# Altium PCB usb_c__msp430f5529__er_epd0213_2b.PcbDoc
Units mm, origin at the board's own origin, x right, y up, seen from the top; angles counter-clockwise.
Board outline 82 x 52 mm, 2 copper layers (Top, Bottom), stack 0 mm thick; 44 components, 39 nets, 231 pads, 105 vias.
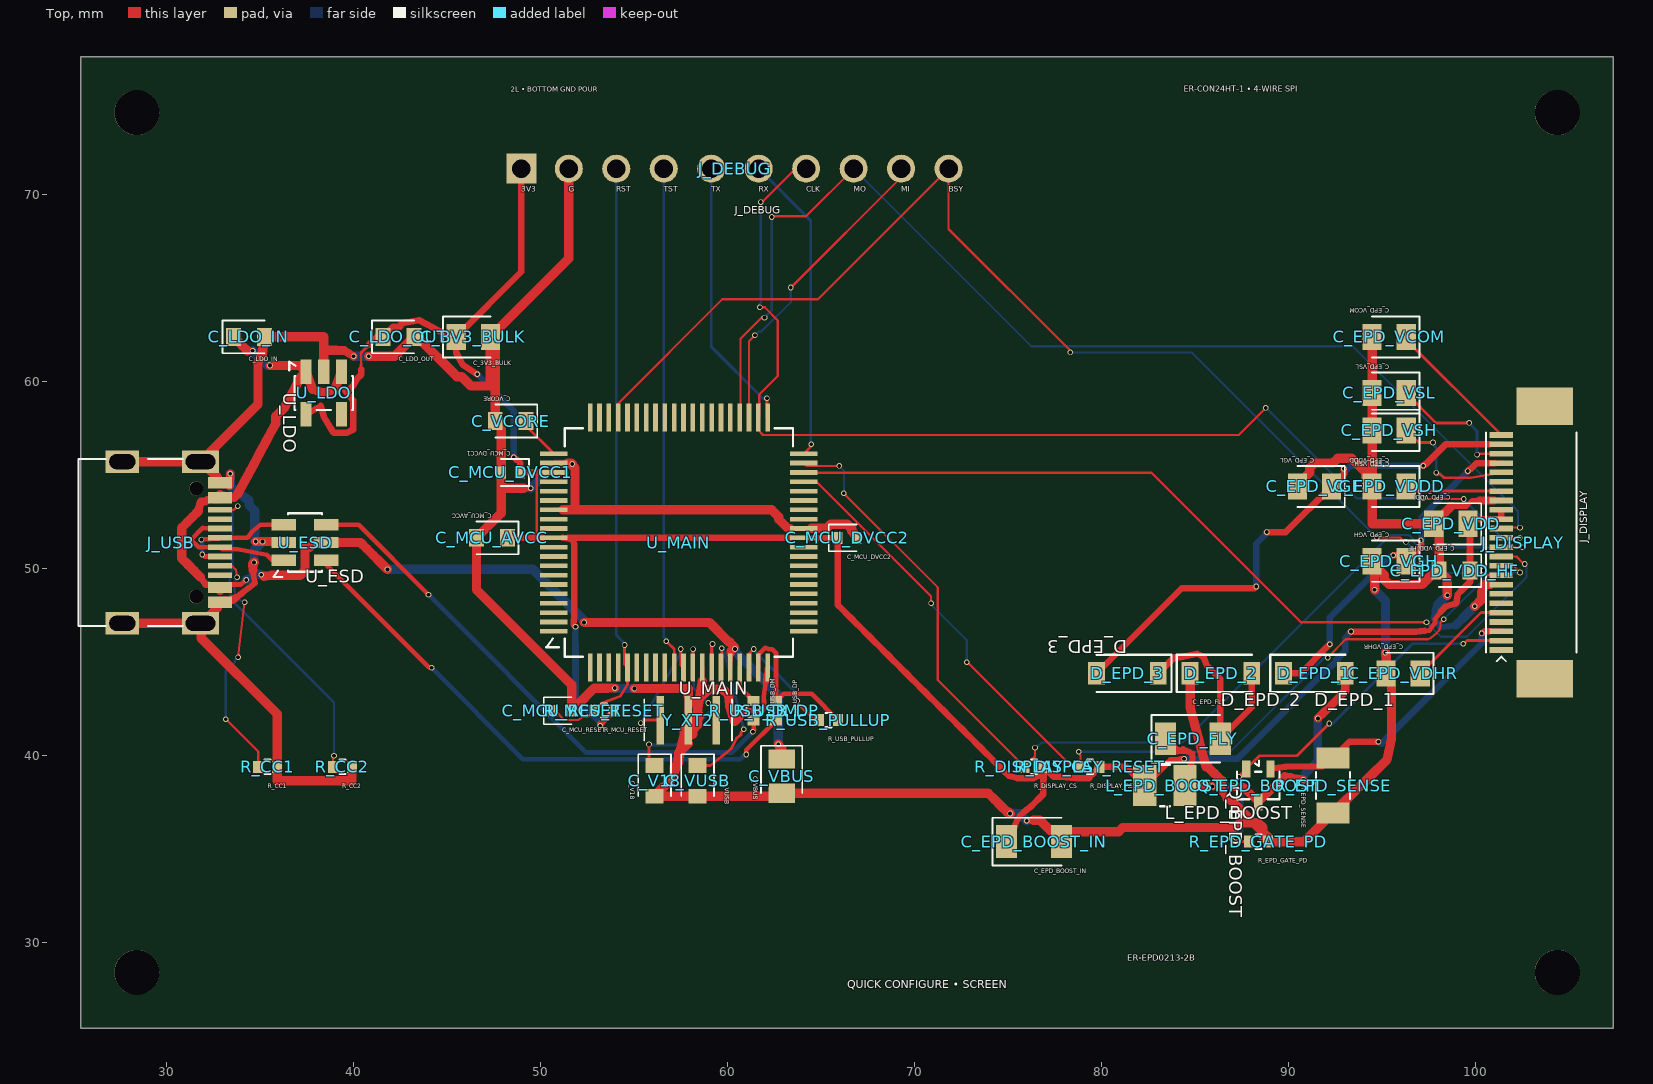
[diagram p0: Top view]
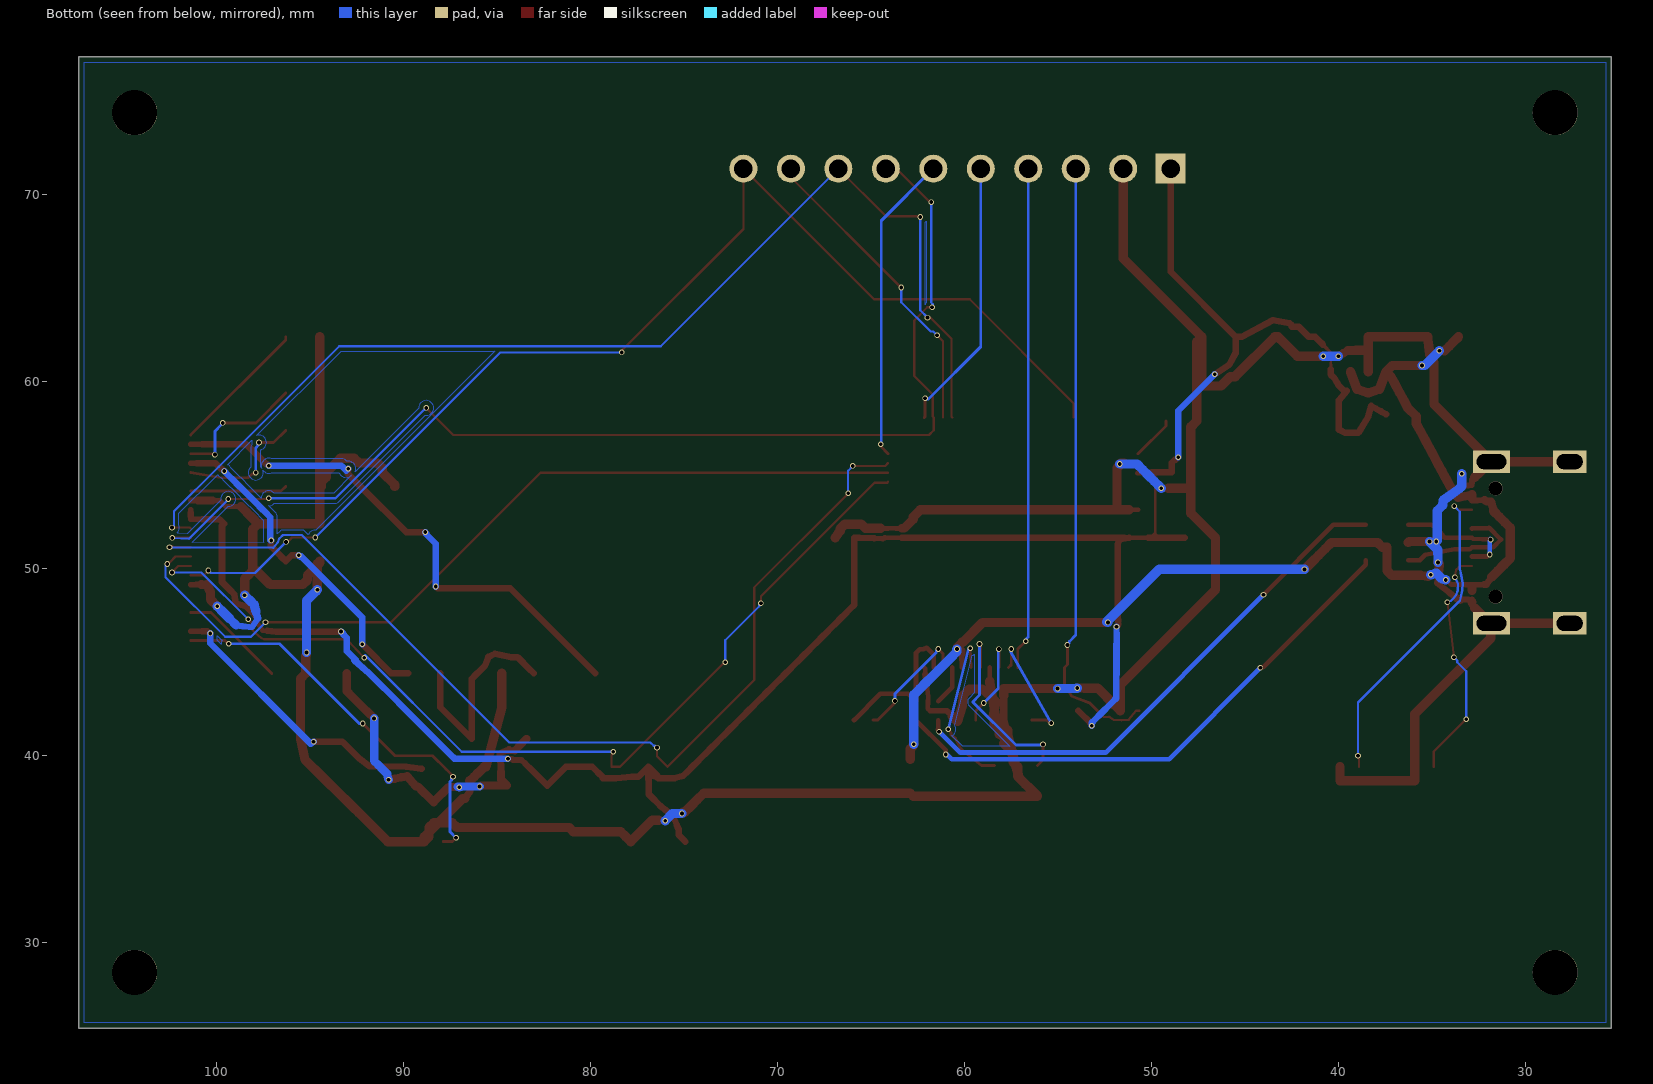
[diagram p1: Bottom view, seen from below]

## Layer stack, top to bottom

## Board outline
25.4,77.4 107.4,77.4 107.4,25.4 25.4,25.4

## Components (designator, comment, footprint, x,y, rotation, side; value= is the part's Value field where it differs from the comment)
C_3V3_BULK "" TSCIRCUIT-2.8500x1.4000mm 46.4,62.4 r0 top
C_EPD_BOOST_IN "" TSCIRCUIT-4.0500x1.7500mm 76.4,35.4 r0 top
C_EPD_FLY "" TSCIRCUIT-4.0500x1.7500mm 84.9,40.9 r0 top
C_EPD_VCOM "" TSCIRCUIT-2.8500x1.4000mm 95.4,62.4 r180 top
C_EPD_VDD "" TSCIRCUIT-2.8500x1.4000mm 98.7,52.4 r180 top
C_EPD_VDD_HF "" TSCIRCUIT-2.4500x0.9500mm 98.9,49.9 r180 top
C_EPD_VDDD "" TSCIRCUIT-2.8500x1.4000mm 95.4,54.4 r180 top
C_EPD_VDHR "" TSCIRCUIT-2.8500x1.4000mm 96.15,44.4 r180 top
C_EPD_VGH "" TSCIRCUIT-2.8500x1.4000mm 95.4,50.4 r180 top
C_EPD_VGL "" TSCIRCUIT-2.8500x1.4000mm 91.4,54.4 r180 top
C_EPD_VSH "" TSCIRCUIT-2.8500x1.4000mm 95.4,57.4 r180 top
C_EPD_VSL "" TSCIRCUIT-2.8500x1.4000mm 95.4,59.4 r180 top
C_LDO_IN "" TSCIRCUIT-2.4500x0.9500mm 34.4,62.4 r0 top
C_LDO_OUT "" TSCIRCUIT-2.4500x0.9500mm 42.4,62.4 r0 top
C_MCU_AVCC "" TSCIRCUIT-2.4500x0.9500mm 47.4,51.65 r180 top
C_MCU_DVCC1 "" TSCIRCUIT-1.5600x0.6400mm 48.4,55.15 r180 top
C_MCU_DVCC2 "" TSCIRCUIT-1.5600x0.6400mm 66.4,51.65 r0 top
C_MCU_RESET "" TSCIRCUIT-1.5600x0.6400mm 51.15,42.4 r0 top
C_V18 "" TSCIRCUIT-0.9500x2.4500mm 56.1,38.65 r270 top
C_VBUS "" TSCIRCUIT-1.4000x2.8500mm 62.9,38.9 r270 top
C_VCORE "" TSCIRCUIT-2.4500x0.9500mm 48.4,57.9 r180 top
C_VUSB "" TSCIRCUIT-0.9500x2.4500mm 58.4,38.65 r270 top
D_EPD_1 "" TSCIRCUIT-4.2000x1.2000mm 91.4,44.4 r0 top
D_EPD_2 "" TSCIRCUIT-4.2000x1.2000mm 86.4,44.4 r0 top
D_EPD_3 "" TSCIRCUIT-4.2000x1.2000mm 81.4,44.4 r180 top
J_DEBUG "" TSCIRCUIT-24.3600x1.5000mm 60.4,71.4 r0 top
J_DISPLAY "" TSCIRCUIT-4.4500x16.5800mm 103,51.4 r90 top
J_USB "" TSCIRCUIT-6.7732x9.8502mm 30.113,51.4 r90 top
L_EPD_BOOST "" TSCIRCUIT-3.4000x2.2000mm 83.4,38.4 r0 top
Q_EPD_BOOST "" TSCIRCUIT-1.7500x2.7000mm 88.4,38.4 r270 top
R_CC1 "" TSCIRCUIT-1.5600x0.6400mm 35.4,39.4 r0 top
R_CC2 "" TSCIRCUIT-1.5600x0.6400mm 39.4,39.4 r0 top
R_DISPLAY_CS "" TSCIRCUIT-1.5600x0.6400mm 76.4,39.4 r0 top
R_DISPLAY_RESET "" TSCIRCUIT-1.5600x0.6400mm 79.4,39.4 r0 top
R_EPD_GATE_PD "" TSCIRCUIT-1.5600x0.6400mm 88.4,35.4 r0 top
R_EPD_SENSE "" TSCIRCUIT-1.7500x4.0500mm 92.4,38.4 r270 top
R_MCU_RESET "" TSCIRCUIT-1.5600x0.6400mm 53.4,42.4 r0 top
R_USB_DM "" TSCIRCUIT-0.6400x1.5600mm 61.4,42.4 r90 top
R_USB_DP "" TSCIRCUIT-0.6400x1.5600mm 62.6,42.4 r90 top
R_USB_PULLUP "" TSCIRCUIT-1.5600x0.6400mm 65.4,41.9 r0 top
U_ESD "" TSCIRCUIT-3.6000x2.5000mm 37.4,51.4 r0 top
U_LDO "" TSCIRCUIT-2.5000x3.6000mm 38.4,59.4 r270 top
U_MAIN "" TSCIRCUIT-14.8500x14.8500mm 57.4,51.4 r0 top
Y_XT2 "" TSCIRCUIT-3.4000x2.6000mm 57.9,41.9 r270 top

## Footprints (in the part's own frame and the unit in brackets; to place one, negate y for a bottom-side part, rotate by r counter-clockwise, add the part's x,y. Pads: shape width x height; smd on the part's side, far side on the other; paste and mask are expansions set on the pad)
TSCIRCUIT-0.6400x1.5600mm [mm]
  rect 0.54x0.64 smd: 1(-0.51,0) 2(0.51,0)
  silkscreen extent -0.15,-0.38 0.15,0.38
TSCIRCUIT-0.9500x2.4500mm [mm]
  rect 0.8x0.95 smd: 1(-0.825,0) 2(0.825,0)
  silkscreen extent -1.43,-0.87 0.82,0.87
TSCIRCUIT-1.4000x2.8500mm [mm]
  rect 1.025x1.4 smd: 1(-0.913,0) 2(0.913,0)
  silkscreen extent -1.62,-1.1 0.91,1.1
TSCIRCUIT-1.5600x0.6400mm [mm]
  rect 0.54x0.64 smd: 1(-0.51,0) 2(0.51,0)
  silkscreen extent -0.98,-0.72 0.51,0.72
TSCIRCUIT-1.7500x2.7000mm [mm]
  rect 0.925x0.45 smd: 1(-0.888,-0.65) 2(-0.888,0.65) 3(0.887,0)
  silkscreen extent -1.32,-1.14 0.73,1.13
TSCIRCUIT-1.7500x4.0500mm [mm]
  rect 1.125x1.75 smd: 1(-1.463,0) 2(1.462,0)
  silkscreen extent -0.73,-0.91 0.73,0.91
TSCIRCUIT-2.4500x0.9500mm [mm]
  rect 0.8x0.95 smd: 1(-0.825,0) 2(0.825,0)
  silkscreen extent -1.42,-0.87 0.82,0.87
TSCIRCUIT-2.5000x3.6000mm [mm]
  rect 1.325x0.6 smd: 1(-1.137,-0.95) 2(-1.137,0) 3(-1.137,0.95) 4(1.138,0.95) 5(1.138,-0.95)
  silkscreen extent -1.69,-1.84 0.91,1.56
TSCIRCUIT-2.8500x1.4000mm [mm]
  rect 1.025x1.4 smd: 1(-0.913,0) 2(0.913,0)
  silkscreen extent -1.63,-1.1 0.91,1.1
TSCIRCUIT-3.4000x2.2000mm [mm]
  rect 1.25x2.2 smd: 1(-1.075,0) 2(1.075,0)
  silkscreen extent -0.26,-1.11 0.26,1.11
TSCIRCUIT-3.4000x2.6000mm [mm]
  rect 2.6x0.4 smd: 1(0,1.5) 2(0,0) 3(0,-1.5)
  silkscreen extent -1.1,-2.35 1.1,2.35
TSCIRCUIT-3.6000x2.5000mm [mm]
  rect 1.325x0.6 smd: 1(-1.137,-0.95) 2(-1.137,0) 3(-1.137,0.95) 4(1.138,0.95) 5(1.138,0) 6(1.138,-0.95)
  silkscreen extent -1.69,-1.84 0.91,1.56
TSCIRCUIT-4.0500x1.7500mm [mm]
  rect 1.125x1.75 smd: 1(-1.462,0) 2(1.463,0)
  silkscreen extent -2.22,-1.28 1.46,1.27
TSCIRCUIT-4.2000x1.2000mm [mm]
  rect 0.9x1.2 smd: 1(-1.65,0) 2(1.65,0)
  silkscreen extent -2.36,-1 1.65,1
TSCIRCUIT-4.4500x16.5800mm [mm]
  rect 0.3x1.25 smd: 1(-5.75,1.6) 2(-5.25,1.6) 3(-4.75,1.6) 4(-4.25,1.6) 5(-3.75,1.6) 6(-3.25,1.6) 7(-2.75,1.6) 8(-2.25,1.6) 9(-1.75,1.6) 10(-1.25,1.6) 11(-0.75,1.6) 12(-0.25,1.6) 13(0.25,1.6) 14(0.75,1.6) 15(1.25,1.6) 16(1.75,1.6) 17(2.25,1.6) 18(2.75,1.6) 19(3.25,1.6) 20(3.75,1.6) 21(4.25,1.6) 22(4.75,1.6) 23(5.25,1.6) 24(5.75,1.6)
  rect 2x3 smd: 25(7.29,-0.725) 26(-7.29,-0.725)
  silkscreen extent -6.35,-2.43 5.9,2.42
TSCIRCUIT-6.7732x9.8502mm [mm]
  rect 0.3x1.3 smd: 1(-3.35,-2.737) 2(-3.05,-2.737) 3(-2.55,-2.737) 4(-2.25,-2.737) 5(-1.75,-2.737) 6(-1.25,-2.737) 7(-0.75,-2.737) 8(-0.25,-2.737) 9(0.25,-2.737) 10(0.75,-2.737) 11(1.25,-2.737) 12(1.75,-2.737) 13(2.55,-2.737) 14(2.25,-2.737) 15(3.35,-2.737) 16(3.05,-2.737)
  rect 1.2x2 hole 0.8 slot 1.6 at 90 deg: 17(-4.325,-1.693) 18(4.325,-1.693)
  rect 1.2x1.8 hole 0.8 slot 1.4 at 90 deg: 19(4.325,2.487) 20(-4.325,2.487)
  round 0.75 hole 0.75 unplated: NPTH-1(-2.9,-1.468) NPTH-2(2.9,-1.468)
  silkscreen extent -4.47,-0.75 4.47,4.83
TSCIRCUIT-14.8500x14.8500mm [mm]
  rect 1.475x0.25 smd: 1(-6.687,-4.75) 2(-6.687,-4.25) 3(-6.687,-3.75) 4(-6.687,-3.25) 5(-6.687,-2.75) 6(-6.687,-2.25) 7(-6.687,-1.75) 8(-6.687,-1.25) 9(-6.687,-0.75) 10(-6.687,-0.25) 11(-6.687,0.25) 12(-6.687,0.75) 13(-6.687,1.25) 14(-6.687,1.75) 15(-6.687,2.25) 16(-6.687,2.75) 17(-6.687,3.25) 18(-6.687,3.75) 19(-6.687,4.25) 20(-6.687,4.75) 41(6.687,4.75) 42(6.687,4.25) 43(6.687,3.75) 44(6.687,3.25) 45(6.687,2.75) 46(6.687,2.25) 47(6.687,1.75) 48(6.687,1.25) 49(6.687,0.75) 50(6.687,0.25) 51(6.687,-0.25) 52(6.687,-0.75) 53(6.687,-1.25) 54(6.687,-1.75) 55(6.687,-2.25) 56(6.687,-2.75) 57(6.687,-3.25) 58(6.687,-3.75) 59(6.687,-4.25) 60(6.687,-4.75)
  rect 0.25x1.475 smd: 21(-4.75,6.687) 22(-4.25,6.687) 23(-3.75,6.687) 24(-3.25,6.687) 25(-2.75,6.687) 26(-2.25,6.687) 27(-1.75,6.687) 28(-1.25,6.687) 29(-0.75,6.687) 30(-0.25,6.687) 31(0.25,6.687) 32(0.75,6.687) 33(1.25,6.687) 34(1.75,6.687) 35(2.25,6.687) 36(2.75,6.687) 37(3.25,6.687) 38(3.75,6.687) 39(4.25,6.687) 40(4.75,6.687) 61(4.75,-6.687) 62(4.25,-6.687) 63(3.75,-6.687) 64(3.25,-6.687) 65(2.75,-6.687) 66(2.25,-6.687) 67(1.75,-6.687) 68(1.25,-6.687) 69(0.75,-6.687) 70(0.25,-6.687) 71(-0.25,-6.687) 72(-0.75,-6.687) 73(-1.25,-6.687) 74(-1.75,-6.687) 75(-2.25,-6.687) 76(-2.75,-6.687) 77(-3.25,-6.687) 78(-3.75,-6.687) 79(-4.25,-6.687) 80(-4.75,-6.687)
  silkscreen extent -7.09,-6.11 6.11,6.11
TSCIRCUIT-24.3600x1.5000mm [mm]
  rect 1.6x1.6 hole 1: 1(-11.43,0)
  round 1.5 hole 1: 2(-8.89,0) 3(-6.35,0) 4(-3.81,0) 5(-1.27,0) 6(1.27,0) 7(3.81,0) 8(6.35,0) 9(8.89,0) 10(11.43,0)

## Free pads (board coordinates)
  round 2.4 hole 2.4 unplated: NPTH-3(28.4,28.4) NPTH-4(104.4,28.4) NPTH-5(28.4,74.4) NPTH-6(104.4,74.4)

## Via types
v1: diameter 0.3, hole 0.2, Top to Bottom, 105 vias

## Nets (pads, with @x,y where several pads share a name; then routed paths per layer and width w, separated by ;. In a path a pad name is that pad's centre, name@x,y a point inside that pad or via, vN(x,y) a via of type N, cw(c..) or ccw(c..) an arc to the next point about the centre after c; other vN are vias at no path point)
".J_DEBUG > .pin4 to .U_MAIN > .pin71": J_DEBUG.4 U_MAIN.71 | length 26.9
  Top w0.15: v1(56.72,46.123) 57.15,45.693 U_MAIN.71
  Bottom w0.15: J_DEBUG.4 56.59,46.35 56.676,46.264 56.676,46.167 v1(56.72,46.123)
".J_DEBUG > .pin5 to .U_MAIN > .pin40": J_DEBUG.5 U_MAIN.40 | length 14.7
  Top w0.15: v1(62.108,59.119) 62.108,58.129 U_MAIN.40
  Bottom w0.15: J_DEBUG.5 59.13,61.87 61.93,59.07 62.059,59.07 v1(62.108,59.119)
".J_DEBUG > .pin6 to .U_MAIN > .pin41": J_DEBUG.6 U_MAIN.41 | length 16.6
  Top w0.15: U_MAIN.41 64.475,56.537 v1(64.475,56.651)
  Bottom w0.15: J_DEBUG.6 64.456,68.614 64.456,56.805 64.456,56.67 v1(64.475,56.651)
".J_DISPLAY > .pin5 to .C_EPD_VDHR > .pin1": C_EPD_VDHR.1 J_DISPLAY.5 | length 5.7
  Top w0.15: C_EPD_VDHR.1 100.313,47.65 J_DISPLAY.5
".J_DISPLAY > .pin18 to .C_EPD_VDDD > .pin1": C_EPD_VDDD.1 J_DISPLAY.18 | length 5.2
  Top w0.15: C_EPD_VDDD.1 96.563,54.15 J_DISPLAY.18
".J_DISPLAY > .pin20 to .C_EPD_VSH > .pin1": C_EPD_VSH.1 J_DISPLAY.20 | length 7
  Top w0.15: C_EPD_VSH.1 96.964,56.749 v1(97.742,56.749) ; v1(97.914,55.141) 97.984,55.071 98.12,55.071 98.327,54.865 99.768,54.865 J_DISPLAY.20
  Bottom w0.15: v1(97.742,56.749) 97.796,56.695 97.796,56.591 97.914,56.472 v1(97.914,55.141)
".J_DISPLAY > .pin22 to .C_EPD_VSL > .pin1": C_EPD_VSL.1 J_DISPLAY.22 | length 7.2
  Top w0.15: C_EPD_VSL.1 97.914,57.799 v1(99.681,57.799) ; v1(100.104,56.104) 100.112,56.112 100.166,56.112 100.203,56.15 J_DISPLAY.22
  Bottom w0.15: v1(99.681,57.799) 99.75,57.73 99.75,57.706 100.104,57.352 v1(100.104,56.104)
".J_DISPLAY > .pin24 to .C_EPD_VCOM > .pin1": C_EPD_VCOM.1 J_DISPLAY.24 | length 7.4
  Top w0.15: C_EPD_VCOM.1 96.312,62.238 J_DISPLAY.24
DISPLAY_BUSY_N: J_DEBUG.10 J_DISPLAY.9 U_MAIN.24 | length 64.3
  Top w0.12: U_MAIN.24 54.15,58.837 59.725,64.412 64.842,64.412 J_DEBUG.10 71.83,68.177 78.394,61.613 78.381,61.613 v1(78.337,61.569) ; v1(94.736,51.669) 95.976,51.669 96.158,51.487 96.241,51.487 v1(96.295,51.433) ; v1(100.45,49.9) 100.7,49.65 J_DISPLAY.9
  Bottom w0.12: v1(78.337,61.569) 84.836,61.569 94.733,51.672 v1(94.736,51.669) ; v1(96.295,51.433) 97.96,49.768 100.318,49.768 v1(100.45,49.9)
DISPLAY_CS_N: J_DISPLAY.12 R_DISPLAY_CS.1 U_MAIN.42 | length 55.7
  Top w0.12: U_MAIN.42 64.239,55.499 v1(65.985,55.499) ; v1(66.227,54.039) 66.31,53.956 66.31,53.934 71.244,49 71.244,48.978 71.244,44.046 R_DISPLAY_CS.1 76.453,39.963 v1(76.453,40.427) ; J_DISPLAY.12 102.336,51.15 102.381,51.195 v1(102.532,51.151)
  Bottom w0.12: v1(65.985,55.499) 66.018,55.466 66.018,55.451 66.227,55.242 v1(66.227,54.039) ; v1(76.453,40.427) 76.553,40.528 76.631,40.528 76.807,40.704 84.355,40.704 95.455,51.804 96.463,51.804 96.633,51.634 96.674,51.593 96.724,51.422 96.979,51.116 v1(102.532,51.151)
DISPLAY_DC: J_DISPLAY.11 U_MAIN.43 | length 45.8
  Top w0.12: U_MAIN.43 64.102,55.136 82.681,55.137 90.685,47.138 v1(97.395,47.134) ; J_DISPLAY.11 102.206,50.65 102.52,50.336 102.559,50.336 v1(102.65,50.248)
  Bottom w0.12: v1(97.395,47.134) 97.513,47.016 98.173,46.356 98.815,46.356 99.552,46.356 102.742,49.546 102.742,50.153 v1(102.65,50.248)
DISPLAY_MISO: J_DEBUG.9 U_MAIN.38 | length 16.8
  Top w0.12: U_MAIN.38 61.15,62.17 v1(61.466,62.486) ; v1(63.379,65.044) 63.436,65.101 63.455,65.101 69.29,70.937 J_DEBUG.9
  Bottom w0.12: v1(61.466,62.486) 61.674,62.694 61.813,62.694 63.379,64.26 v1(63.379,65.044)
DISPLAY_MOSI: J_DEBUG.8 J_DISPLAY.14 U_MAIN.37 | length 62.1
  Top w0.12: U_MAIN.37 60.702,58.139 60.702,62.301 61.833,63.432 v1(61.98,63.432) ; v1(62.371,68.813) 62.414,68.856 62.554,68.856 64.206,68.856 J_DEBUG.8 ; J_DISPLAY.14 101.45,52.2 v1(102.4,52.2)
  Bottom w0.12: v1(61.98,63.432) 62.012,63.464 62.371,63.823 v1(62.371,68.813) ; J_DEBUG.8 76.252,61.898 93.314,61.898 93.458,61.898 99.896,55.459 102.29,53.065 102.29,52.219 102.381,52.219 v1(102.4,52.2)
DISPLAY_RESET_N: J_DISPLAY.10 R_DISPLAY_RESET.1 U_MAIN.44 | length 52
  Top w0.12: U_MAIN.44 64.137,54.601 64.816,54.601 70.892,48.526 v1(70.892,48.151) ; v1(72.8,45) 72.889,44.911 72.923,44.911 78.433,39.4 R_DISPLAY_RESET.1 78.89,40.022 78.799,40.112 v1(78.799,40.203) ; v1(92.112,45.229) 93.062,46.221 97.435,46.221 97.457,46.221 97.621,46.285 97.943,46.557 98.076,46.705 98.148,46.912 98.148,47.121 v1(98.325,47.298) ; J_DISPLAY.10 102.05,50.15 v1(102.399,49.798)
  Bottom w0.12: v1(70.892,48.151) 70.98,48.063 70.98,47.995 72.8,46.175 v1(72.8,45) ; v1(78.799,40.203) 86.891,40.203 92.068,45.38 92.068,45.273 v1(92.112,45.229) ; v1(98.325,47.298) 100.827,49.8 102.308,49.8 v1(102.399,49.798)
DISPLAY_SCLK: J_DEBUG.7 J_DISPLAY.13 U_MAIN.39 | length 61.8
  Top w0.12: v1(61.735,63.982) 61.993,63.982 62.693,63.282 62.693,60.31 61.698,59.314 61.698,58.135 U_MAIN.39 61.65,57.41 61.903,57.158 87.358,57.158 v1(88.8,58.6) ; v1(61.78,69.614) 61.849,69.683 61.921,69.683 63.639,71.4 J_DEBUG.7 ; v1(97.225,53.766) 97.262,53.729 97.392,53.729 v1(99.391,53.729) ; J_DISPLAY.13 102.329,51.65 102.379,51.6 v1(102.387,51.645)
  Bottom w0.12: v1(61.735,63.982) 61.695,64.022 61.695,64.15 61.78,64.236 v1(61.78,69.614) ; v1(88.8,58.6) 88.916,58.484 88.932,58.484 93.65,53.766 v1(97.225,53.766) ; v1(99.391,53.729) 99.483,53.637 99.483,53.609 101.492,51.6 v1(102.387,51.645)
EPD_GDR: J_DISPLAY.2 Q_EPD_BOOST.1 R_EPD_GATE_PD.1 | length 21.3
  Top w0.15: v1(87.2,35.6) 87.217,35.583 87.4,35.4 R_EPD_GATE_PD.1 ; v1(87.364,38.863) 87.364,38.901 Q_EPD_BOOST.1 88.456,39.994 90.471,39.994 v1(92.193,41.716) ; v1(99.363,45.987) 99.41,46.034 99.448,46.034 99.565,46.15 J_DISPLAY.2
  Bottom w0.15: v1(87.2,35.6) 87.525,35.925 87.525,38.464 87.525,38.605 87.449,38.681 87.449,38.778 v1(87.364,38.863) ; v1(92.193,41.716) 92.195,41.718 92.382,41.718 96.651,45.987 v1(99.363,45.987)
EPD_PUMP: C_EPD_FLY.2 D_EPD_2.2 D_EPD_3.1 | length 11.7
  Top w0.35: D_EPD_3.1 83.268,44.618 83.486,44.836 83.704,45.054 83.922,45.272 84.239,45.272 85.125,45.45 85.475,45.275 85.658,44.802 85.893,44.567 86.128,44.333 86.363,44.098 86.363,43.778 86.363,43.458 86.363,43.138 86.363,42.819 86.363,42.499 86.363,42.179 86.363,41.859 86.363,41.54 86.363,41.22 C_EPD_FLY.2 88.05,42.587 D_EPD_2.2
EPD_RESE: J_DISPLAY.3 Q_EPD_BOOST.2 R_EPD_SENSE.1 | length 15.7
  Top w0.3: 100.775,46.65 100.837,46.65 100.931,46.65 101.025,46.65 101.119,46.65 101.213,46.65 101.306,46.65 J_DISPLAY.3
  Top w0.35: Q_EPD_BOOST.2 89.858,39.413 91.824,39.426 R_EPD_SENSE.1 93.279,40.741 v1(94.825,40.741) ; v1(100.353,46.535) 100.394,46.576 100.431,46.576 100.505,46.65 100.65,46.65 100.744,46.65 100.775,46.65
  Bottom w0.35: v1(94.825,40.741) 94.969,40.648 94.994,40.648 100.353,46.008 v1(100.353,46.535)
EPD_SWITCH: C_EPD_FLY.1 D_EPD_1.2 L_EPD_BOOST.2 Q_EPD_BOOST.3 | length 17.8
  Top w0.337: 84.37,40.346 84.624,40.22 84.878,40.094 84.878,39.756 84.799,39.52
  Top w0.35: 84.069,40.269 84.443,40.269 84.37,40.346
  Top w0.375: L_EPD_BOOST.2@84.798,39.121 84.799,39.52
  Top w0.413: C_EPD_FLY.1 83.753,40.584 84.069,40.269
  Top w0.45: L_EPD_BOOST.2@84.798,39.121 84.796,38.721 84.636,38.561 L_EPD_BOOST.2 85.877,38.4 85.93,38.346 v1(85.943,38.347) ; v1(87.032,38.311) 87.593,38.319 Q_EPD_BOOST.3 88.681,37.788 88.962,38.064 89.243,38.34 89.35,38.35 89.805,38.892 90.14,38.831 90.475,38.769 v1(90.81,38.707) ; v1(91.589,41.988) 91.602,42.001 91.891,42.29 92.181,42.58 92.471,42.87 92.76,43.159 93.05,43.449 93.05,43.766 93.05,44.083 D_EPD_1.2
  Bottom w0.45: v1(85.943,38.347) 86.936,38.347 86.94,38.343 87.109,38.343 v1(87.032,38.311) ; v1(90.81,38.707) 90.894,39 90.894,39.027 91.126,39.258 91.357,39.49 91.589,39.722 91.589,40.099 91.589,40.477 91.589,40.855 91.589,41.233 91.589,41.61 v1(91.589,41.988)
EPD_VGH: C_EPD_VGH.1 D_EPD_1.1 J_DISPLAY.21 | length 18.4
  Top w0.3: J_DISPLAY.21@101.071,55.65 J_DISPLAY.21
  Top w0.325: v1(97.09,51.51) 97.124,51.211
  Top w0.35: D_EPD_1.1 90.683,44.405 92.13,45.874 92.146,45.88 v1(92.221,45.955) ; v1(95.619,50.721) 95.992,50.721 C_EPD_VGH.1 96.515,50.603 96.718,50.805 96.921,51.008 97.124,51.211 ; v1(99.605,55.221) 99.728,55.344 99.777,55.344 99.93,55.497 100.083,55.65 100.412,55.65 100.741,55.65 J_DISPLAY.21@101.071,55.65
  Bottom w0.35: v1(92.221,45.955) 92.221,47.391 95.481,50.65 95.548,50.65 v1(95.619,50.721) ; v1(97.09,51.51) 97.14,51.522 97.14,51.83 97.14,52.139 97.14,52.448 97.14,52.756 97.387,53.003 97.633,53.249 97.88,53.496 98.126,53.742 98.373,53.989 98.619,54.235 98.866,54.482 99.112,54.728 99.359,54.975 v1(99.605,55.221)
EPD_VGL: C_EPD_VGL.1 D_EPD_3.2 J_DISPLAY.23 | length 28.4
  Top w0.3: 100.775,56.65 100.837,56.65 100.931,56.65 101.025,56.65 101.119,56.65 101.213,56.65 101.306,56.65 J_DISPLAY.23
  Top w0.35: D_EPD_3.2 84.3,48.95 88.115,48.95 88.189,48.95 v1(88.283,49.044) ; v1(88.852,51.958) 89.871,51.958 C_EPD_VGL.1 92.985,55.072 v1(92.966,55.348) ; v1(97.22,55.505) 97.292,55.577 97.345,55.577 98.418,56.65 100.65,56.65 100.744,56.65 100.775,56.65
  Bottom w0.35: v1(88.283,49.044) 88.289,51.334 88.794,51.839 88.794,51.9 v1(88.852,51.958) ; v1(92.966,55.348) 93.076,55.307 93.076,55.247 93.334,55.505 v1(97.22,55.505)
GND: C_3V3_BULK.2 C_EPD_BOOST_IN.2 C_EPD_VCOM.2 C_EPD_VDD.2 C_EPD_VDD_HF.2 C_EPD_VDDD.2 C_EPD_VDHR.2 C_EPD_VGH.2 C_EPD_VGL.2 C_EPD_VSH.2 C_EPD_VSL.2 C_LDO_IN.2 C_LDO_OUT.2 C_MCU_AVCC.2 C_MCU_DVCC1.2 C_MCU_DVCC2.2 C_MCU_RESET.2 C_V18.2 C_VBUS.2 C_VCORE.2 C_VUSB.2 D_EPD_2.1 J_DEBUG.2 J_DISPLAY.8 J_DISPLAY.17 J_USB.1 J_USB.2 J_USB.15 J_USB.16 J_USB.17 J_USB.18 J_USB.19 J_USB.20 R_CC1.2 R_CC2.2 R_EPD_GATE_PD.2 R_EPD_SENSE.2 U_ESD.2 U_LDO.2 U_MAIN.14 U_MAIN.19 U_MAIN.49 U_MAIN.61 U_MAIN.68 Y_XT2.2 | length 268.7
  Top w0.25: U_MAIN.14@51.203,53.15 U_MAIN.14 U_MAIN.14@51.45,53.15 ; U_MAIN.68@58.65,43.975 U_MAIN.68 ; 61.962,42.525 61.955,42.846 61.948,43.166 61.999,43.555 62.049,43.945 ; U_MAIN.61@62.099,44.334 62.099,44.661 U_MAIN.61 ; U_MAIN.49@63.658,52.158 U_MAIN.49 ; 98.717,53.33 99.533,53.33 99.852,53.65 100.239,53.65 ; U_MAIN.19 51.144,55.65 51.45,55.65 51.369,55.65 51.275,55.65 51.181,55.65 51.088,55.65 50.994,55.65 50.9,55.65 50.806,55.65 U_MAIN.19
  Top w0.269: U_MAIN.49 U_MAIN.49@64.494,52.155
  Top w0.275: J_USB.1@32.849,48.2 J_USB.2 ; 60.95,42.4 61.306,42.4 61.572,42.4 61.837,42.4 61.962,42.525
  Top w0.277: U_MAIN.49@63.35,52.163 U_MAIN.49@63.658,52.158
  Top w0.288: J_USB.15@32.849,54.6 J_USB.16 J_USB.16@32.945,54.461
  Top w0.3: J_USB.1@32.699,47.9 J_USB.1 J_USB.2@32.849,48.2 ; 32.699,54.9 J_USB.15 J_USB.16@32.849,54.6 ; J_USB.2 32.945,48.339 33.037,48.35 33.13,48.35 33.224,48.35 33.318,48.35 33.412,48.35 33.499,48.35 ; J_USB.16@32.945,54.461 33.037,54.45 33.13,54.45 33.224,54.45 33.318,54.45 J_USB.16@33.349,54.45 ; 60.662,42.111 60.95,42.4 ; J_DISPLAY.17@101.013,53.65 J_DISPLAY.17 ; J_DISPLAY.8@101.108,49.15 J_DISPLAY.8
  Top w0.31: 34.383,48.964 34.73,49.231
  Top w0.312: 34.631,49.658 34.73,49.231 ; 49.102,54.305 v1(49.469,54.305)
  Top w0.322: J_DISPLAY.8@100.817,49.145 J_DISPLAY.8@101.108,49.15
  Top w0.325: 34.036,48.696 34.383,48.964 ; 34.612,49.932 34.631,49.658 ; 62.049,43.945 U_MAIN.61@62.099,44.334
  Top w0.35: 33.689,48.429 34.036,48.696 ; v1(76.015,36.52) 76.365,36.534
  Top w0.375: 86.462,38.65 86.462,38.369 86.462,38.088 86.721,37.707
  Top w0.4: Y_XT2.2@57.7,41.149 Y_XT2.2 57.9,43.2 ; Y_XT2.2@57.9,40.65 57.9,40.9 58.15,41.15
  Top w0.425: 33.557,48.35 33.689,48.429 ; 100.239,53.65 100.626,53.65
  Top w0.437: 39.494,61.681 39.745,61.524 v1(39.996,61.367) ; 100.626,53.65 J_DISPLAY.17@101.013,53.65
  Top w0.45: 33.505,48.35 33.557,48.35
  Top w0.475: J_USB.16@33.349,54.45 v1(33.4,55.075) ; 39.056,61.681 39.494,61.681 ; 62.743,52.65 63.009,52.384 63.228,52.166 63.35,52.163 ; 98.407,53.02 98.717,53.33 ; 100.525,49.14 J_DISPLAY.8@100.817,49.145
  Top w0.5: J_USB.20 J_USB.17 ; J_USB.19 J_USB.18 ; J_USB.1@32.699,47.9 32.474,47.675 31.874,47.075 J_USB.17 ; 32.699,54.9 32.474,55.125 31.874,55.725 J_USB.18 ; 33.499,48.35 33.505,48.35 ; 34.612,49.932 34.593,50.206 34.593,50.255 v1(34.674,50.336) ; v1(34.765,51.456) 35.246,51.456 35.726,51.456 36.207,51.456 U_ESD.2 36.213,51.45 v1(35.125,51.45) ; 39.056,61.681 38.4,61.681 U_LDO.2 38.4,62.4 C_LDO_IN.2 35.169,61.93 35.112,61.46 34.882,61.053 34.882,58.801 J_USB.18 ; R_CC2.2 39.91,38.65 35.91,38.65 R_CC1.2 35.91,42.222 31.838,46.294 31.838,47.043 J_USB.17 ; v1(40.804,61.361) 40.809,61.366 40.903,61.366 41.333,61.366 41.762,61.366 42.191,61.366 42.536,61.711 42.88,62.055 C_LDO_OUT.2 43.4,62.4 45.525,60.275 45.775,60.275 46.275,59.775 47.313,59.775 C_3V3_BULK.2 ; 49.102,54.305 48.735,54.305 47.89,54.305 C_MCU_DVCC1.2 ; U_MAIN.14@51.203,53.15 51.693,53.15 52.183,53.15 52.673,53.15 53.164,53.15 62.361,53.15 62.743,52.767 62.743,52.65 ; 51.45,53.15 51.84,53.15 51.84,55.385 51.575,55.65 51.45,55.65 51.463,55.65 51.642,55.65 51.692,55.6 v1(51.7,55.6) ; J_DEBUG.2 51.51,66.597 C_3V3_BULK.2 ; v1(53.968,43.613) 53.602,43.612 53.236,43.611 52.87,43.61 52.567,43.308 52.265,43.005 51.962,42.703 C_MCU_RESET.2 51.66,43.788 46.575,48.873 46.575,49.336 46.575,49.799 46.575,50.262 46.575,50.724 46.575,51.187 C_MCU_AVCC.2 47.89,52.965 C_MCU_DVCC1.2 ; v1(55.019,43.586) 57.9,43.586 57.9,43.2 ; 57.7,41.149 57.074,38.799 56.749,38.474 56.425,38.15 C_V18.2 ; Y_XT2.2@57.9,40.65 57.4,40.15 57.4,39.65 57.15,39.4 57.15,38.9 56.1,37.85 C_V18.2 ; 58.15,41.15 58.15,41.4 58.4,41.65 58.4,42.15 58.412,42.15 58.481,42.081 58.394,42.475 58.306,42.869 58.634,43.197 59.067,43.567 59.733,43.567 60.067,43.233 60.105,42.674 60.239,42.248 60.373,41.823 60.662,42.111 ; C_VUSB.2 C_V18.2 ; U_MAIN.68@58.65,43.975 58.65,43.9 58.314,41.977 58.005,41.668 57.696,41.359 57.696,40.874 57.058,38.783 56.738,38.463 56.419,38.144 C_V18.2 ; U_MAIN.49@64.494,52.155 64.9,52.16 65.301,52.16 65.525,52.384 65.962,52.384 66.4,52.384 66.655,52.129 66.655,52.017 C_MCU_DVCC2.2 ; v1(75.119,36.905) 75.061,36.963 74.976,36.963 74.634,37.305 74.293,37.646 73.951,37.988 73.471,37.988 72.99,37.988 72.51,37.988 72.029,37.988 71.549,37.988 71.068,37.988 70.588,37.988 70.107,37.988 69.627,37.988 69.146,37.988 68.666,37.988 68.185,37.988 67.705,37.988 67.224,37.988 66.744,37.988 66.263,37.988 65.783,37.988 65.302,37.988 64.822,37.988 64.341,37.988 63.861,37.988 63.38,37.988 C_VBUS.2 62.737,37.825 C_V18.2 ; 76.365,36.534 76.715,36.548 C_EPD_BOOST_IN.2 78.128,35.665 78.393,35.93 78.892,35.93 79.391,35.93 79.891,35.93 80.39,35.93 80.889,35.93 80.93,35.93 81.15,36.15 87.15,36.15 87.4,36.4 88.4,36.4 88.65,36.15 88.65,35.9 ; D_EPD_2.1 84.75,43.95 84.75,43.501 84.75,43.051 84.75,42.602 85.6,39.4 85.688,39.402 86.001,39.085 86.232,38.867 86.462,38.65 ; 86.721,37.707 86.843,37.707 88.65,35.9 ; C_EPD_VGL.2 90.487,54.488 91.15,55.15 91.15,55.4 91.4,55.65 92.4,55.65 92.65,55.9 93.4,55.9 94.15,55.15 94.15,54.9 94.4,54.65 94.4,54.4 C_EPD_VDDD.2 ; C_EPD_VSH.2 C_EPD_VDDD.2 ; C_EPD_VSH.2 C_EPD_VSL.2 ; C_EPD_VSL.2 C_EPD_VCOM.2 ; v1(94.621,48.874) 94.621,50.267 C_EPD_VGH.2 94.487,50.313 95.15,49.65 95.15,49.4 95.4,49.15 97.15,49.15 97.9,49.9 C_EPD_VDD_HF.2 ; v1(95.2,45.513) 95.2,45.384 95.238,45.347 C_EPD_VDHR.2 95.525,44.113 95.525,40.9 95.278,39.776 94.959,39.46 94.639,39.145 94.319,38.83 93.999,38.514 93.679,38.199 93.359,37.884 93.04,37.568 92.72,37.253 R_EPD_SENSE.2 90.863,35.4 R_EPD_GATE_PD.2 ; 98.407,53.02 98.097,52.71 C_EPD_VDD.2 ; v1(98.516,48.583) 98.516,49.021 98.516,49.459 98.296,49.679 C_EPD_VDD_HF.2 ; v1(99.98,47.992) 100.343,48.355 100.343,48.757 100.525,49.14 ; C_3V3_BULK.2 47.575,62.138 C_VCORE.2 47.89,57.585 C_MCU_DVCC1.2 ; 88.65,35.9 88.65,35.66 R_EPD_GATE_PD.2 ; 88.65,35.9 88.9,35.65 88.9,35.4 R_EPD_GATE_PD.2 ; C_EPD_VDDD.2 94.487,52.4 C_EPD_VDD.2 ; C_EPD_VDD.2 98.075,52.112 C_EPD_VDD_HF.2
  Bottom w0.312: 97.806,47.337 97.962,47.103 98.119,46.869 98.275,46.869
  Bottom w0.325: 98.275,46.869 98.617,46.92 98.959,46.971
  Bottom w0.4: 97.806,47.337 97.903,47.702
  Bottom w0.45: 98.959,46.971 99.299,47.311
  Bottom w0.475: v1(34.674,50.336) 34.674,50.814
  Bottom w0.5: v1(33.4,55.075) 33.396,54.413 33.458,54.351 33.462,54.347 33.529,54.28 34.4,53.65 34.417,53.392 34.713,53.096 34.713,52.707 34.713,52.319 34.713,51.931 34.713,51.542 34.713,51.508 v1(34.765,51.456) ; 34.674,50.814 34.674,50.999 v1(35.125,51.45) ; v1(39.996,61.367) 39.999,61.364 40.057,61.364 40.06,61.361 40.432,61.361 v1(40.804,61.361) ; v1(49.469,54.305) 49.546,54.372 49.853,54.679 50.16,54.986 50.467,55.293 50.774,55.6 51.237,55.6 v1(51.7,55.6) ; v1(53.968,43.613) 53.973,43.608 54.03,43.608 54.052,43.586 54.536,43.586 v1(55.019,43.586) ; v1(75.119,36.905) 75.631,36.905 v1(76.015,36.52) ; v1(94.621,48.874) 94.687,48.808 94.687,48.799 95.2,48.286 v1(95.2,45.513) ; 97.903,47.702 98,48.067 98.205,48.272 98.41,48.477 v1(98.516,48.583) ; 99.299,47.311 99.64,47.652 v1(99.98,47.992)
MAIN_RESET: C_MCU_RESET.1 J_DEBUG.3 R_MCU_RESET.1 U_MAIN.76 | length 33
  Top w0.12: C_MCU_RESET.1 50.824,42.4 51.22,41.919 51.597,41.886 52.028,41.91 52.275,42.08 52.214,42.062 52.552,42.062 R_MCU_RESET.1
  Top w0.15: R_MCU_RESET.1 53.301,42.811 54.263,43.17 54.651,43.809 U_MAIN.76 54.495,44.867 v1(54.495,45.914)
  Bottom w0.15: J_DEBUG.3 54.05,46.445 54.392,46.103 54.392,46.017 v1(54.495,45.914)
MSP_USB_PUR: R_USB_PULLUP.1 U_MAIN.63 | length 6.5
  Top w0.15: U_MAIN.63 61.15,45.45 v1(61.4,45.7) ; v1(63.723,42.926) 63.757,42.897 63.757,42.787 64.644,41.9 R_USB_PULLUP.1
  Bottom w0.15: v1(61.4,45.7) 61.515,45.585 61.515,45.515 63.723,43.307 v1(63.723,42.926)
MSP_V18: C_V18.1 U_MAIN.67 | length 10.5
  Top w0.15: v1(55.8,40.6) 55.8,39.775 C_V18.1 ; U_MAIN.67 59.15,45.892 59.2,45.942 v1(59.2,45.971)
  Bottom w0.15: v1(55.8,40.6) 55.841,40.559 55.972,40.559 57.249,40.559 59.563,42.873 59.2,43.236 v1(59.2,45.971)
MSP_VCORE: C_VCORE.1 U_MAIN.20 | length 2.4
  Top w0.15: C_VCORE.1 49.225,57.638 U_MAIN.20
MSP_VUSB: C_VUSB.1 U_MAIN.66 | length 8.9
  Top w0.15: C_VUSB.1 59.089,39.475 59.979,40.171 60.197,40.379 60.489,40.931 60.723,41.109 60.723,41.24 v1(60.864,41.409) ; U_MAIN.66 v1(59.698,45.741)
  Bottom w0.15: v1(59.698,45.741) 59.805,45.686 59.805,45.642 v1(60.864,41.409)
usb-dm-mcu: R_USB_DM.2 U_MAIN.64 | length 2.1
  Top w0.25: U_MAIN.64 60.65,43.66 R_USB_DM.2
usb-dm-phy: R_USB_DM.1 U_ESD.4 | length 29
  Top w0.25: U_ESD.4 40.261,52.35 v1(44.005,48.606) ; v1(61.36,41.269) 61.432,41.403 61.4,41.435 R_USB_DM.1
  Bottom w0.25: v1(44.005,48.606) 44.117,48.494 52.453,40.163 54.159,40.163 60.221,40.165 v1(61.36,41.269)
usb-dm-port: J_USB.7 J_USB.9 U_ESD.3 | length 6.6
  Top w0.25: v1(31.854,51.557) 32.794,51.595 J_USB.9 34.316,51.65 34.536,51.944 35.016,52.35 U_ESD.3 ; v1(31.905,50.761) 31.908,50.784 32.048,50.65 J_USB.7
  Bottom w0.25: v1(31.854,51.557) 31.874,51.591 31.874,51.529 31.905,51.498 v1(31.905,50.761)
usb-dp-mcu: R_USB_DP.2 R_USB_PULLUP.2 U_MAIN.62 | length 8.5
  Top w0.25: U_MAIN.62 61.65,44.918 61.65,45.124 61.65,45.329 61.65,45.4 62.025,45.775 62.204,45.69 62.396,45.69 62.477,45.609 62.6,45.486 62.6,45.252 62.6,45.018 62.6,44.784 62.6,44.55 62.6,44.315 62.6,44.081 62.6,43.847 62.6,43.613 62.6,43.378 62.6,43.144 R_USB_DP.2 63.003,43.316 64.433,43.316 64.497,43.313 R_USB_PULLUP.2
usb-dp-phy: R_USB_DP.1 U_ESD.6 | length 29.6
  Top w0.25: U_ESD.6 38.537,50.208 44.023,44.722 44.142,44.722 v1(44.168,44.696) ; v1(61.01,40.057) 61.01,40.3 R_USB_DP.1
  Bottom w0.25: v1(44.168,44.696) 49.058,39.799 60.561,39.796 60.673,39.806 60.946,40.08 60.987,40.08 v1(61.01,40.057)
usb-dp-port: J_USB.8 J_USB.10 U_ESD.1 | length 7.1
  Top w0.25: J_USB.10 31.936,52.18 31.298,51.561 31.709,51.151 J_USB.8 32.965,51.035 33.799,51.035 35.343,50.742 35.636,50.45 U_ESD.1
USB_CC1: J_USB.6 R_CC1.1 | length 12.8
  Top w0.12: J_USB.6 33.492,50.15 33.672,49.97 33.71,49.932 v1(33.764,49.535) ; v1(33.163,41.946) 33.178,41.931 34.89,40.219 R_CC1.1 ; v1(33.819,45.258) v1(34.165,48.21)
  Bottom w0.12: v1(33.163,41.946) 33.163,44.516 33.643,44.996 33.643,45.082 v1(33.819,45.258) ; v1(33.764,49.535) 33.621,49.242 33.599,49.202 33.61,48.838 33.684,48.639 33.817,48.441 33.987,48.271 v1(34.165,48.21)
USB_CC2: J_USB.12 R_CC2.1 | length 17.4
  Top w0.12: J_USB.12 33.597,53.15 v1(33.796,53.349) ; R_CC2.1 38.89,39.828 38.941,39.879 38.941,39.98 v1(38.947,39.986)
  Bottom w0.12: v1(33.796,53.349) 33.791,53.344 33.499,53.052 33.499,49.971 33.454,49.774 33.344,49.217 33.369,48.841 33.486,48.287 33.541,48.245 38.947,42.839 v1(38.947,39.986)
VBUS5: C_LDO_IN.1 C_VBUS.1 J_USB.3 J_USB.4 J_USB.13 J_USB.14 U_ESD.5 U_LDO.1 U_LDO.3 U_MAIN.65 | length 65.2
  Top w0.25: J_USB.4@33.188,49.15 33.526,49.15 33.963,49.15 v1(34.26,49.4) ; U_MAIN.65@60.144,45.11 60.15,45.104 U_MAIN.65 60.15,44.806 60.15,44.9 60.15,44.993 60.15,45.087 60.15,45.181 60.15,45.274 60.15,45.368 U_MAIN.65@60.15,45.45
  Top w0.3: 32.181,53.666 32.556,53.65 J_USB.14 32.849,53.8 ; J_USB.4@32.199,49.15 32.468,49.15 J_USB.4 ; J_USB.3@32.849,49 J_USB.4 ; J_USB.4@33.188,49.15 J_USB.4
  Top w0.313: U_MAIN.65@60.144,45.11 U_MAIN.65@60.159,45.45
  Top w0.325: v1(35.06,49.669) 35.2,49.6 ; 60.15,45.45 60.158,45.458 v1(60.4,45.7)
  Top w0.35: 34.32,61.655 v1(34.595,61.655)
  Top w0.375: 31.798,49.554 32.087,49.15 J_USB.4@32.199,49.15
  Top w0.437: 31.712,53.197 31.838,53.588 32.056,53.588 32.181,53.666
  Top w0.45: 31.678,53.066 31.712,53.197 ; 60.137,46.07 60.384,45.822 60.166,45.603 60.159,45.45
  Top w0.475: J_USB.13 33.225,53.875 33.6,53.8 33.8,54
  Top w0.5: 31.678,53.066 31.386,52.774 31.094,52.481 30.802,52.189 30.802,51.78 30.802,51.37 30.802,50.96 30.802,50.55 31.134,50.218 31.466,49.886 31.798,49.554 ; J_USB.3 J_USB.4@32.849,49 ; J_USB.13@32.849,53.8 J_USB.13 ; C_LDO_IN.1 33.823,62.152 34.072,61.903 34.32,61.655 ; 33.8,54 34.026,54.418 34.251,54.836 34.477,55.254 34.703,55.673 34.928,56.091 35.154,56.509 35.38,56.927 35.605,57.345 35.831,57.763 35.831,58.148 36.282,58.6 36.508,59.018 36.734,59.436 36.959,59.854 U_LDO.1@37.185,60.272 ; 35.2,49.6 35.6,49.64 35.89,49.64 35.9,49.65 37.15,49.65 37.4,49.9 37.4,51.15 37.65,51.15 37.9,51.4 U_ESD.5 38.995,51.4 39.452,51.4 39.91,51.4 40.367,51.4 40.706,51.06 41.046,50.721 41.385,50.381 41.725,50.042 41.731,50.042 v1(41.812,49.961) ; v1(35.527,60.871) 37.117,60.871 U_LDO.1 ; U_LDO.1@37.185,60.272 U_LDO.1 ; U_LDO.3 39,59.6 38.4,59.4 37.8,59.6 U_LDO.1 ; v1(52.33,47.124) 59.034,47.124 60.088,46.07 60.137,46.07 ; v1(62.715,40.611) 62.755,40.571 62.755,40.502 62.9,40.357 62.9,40.085 C_VBUS.1
  Bottom w0.5: v1(34.26,49.4) 34.451,49.454 34.749,49.752 34.816,49.752 v1(35.06,49.669) ; v1(34.595,61.655) 35.379,60.871 v1(35.527,60.871) ; v1(41.812,49.961) 42.289,49.961 42.767,49.961 43.244,49.961 43.721,49.961 49.589,49.961 52.4,47.15 52.356,47.15 v1(52.33,47.124) ; v1(60.4,45.7) 60.409,45.691 60.409,45.552 60.739,45.222 61.068,44.893 61.398,44.564 61.727,44.234 62.056,43.905 62.386,43.576 62.715,43.246 62.715,42.807 62.715,42.368 62.715,41.929 62.715,41.489 62.715,41.05 v1(62.715,40.611)
VCC_3V3: C_3V3_BULK.1 C_EPD_BOOST_IN.1 C_EPD_VDD.1 C_EPD_VDD_HF.1 C_LDO_OUT.1 C_MCU_AVCC.1 C_MCU_DVCC1.1 C_MCU_DVCC2.1 J_DEBUG.1 J_DISPLAY.15 J_DISPLAY.16 L_EPD_BOOST.1 R_DISPLAY_CS.2 R_DISPLAY_RESET.2 R_MCU_RESET.2 U_LDO.5 U_MAIN.11 U_MAIN.18 U_MAIN.50 | length 130.3
  Top w0.12: 40.39,61.48 40.397,61.207 40.403,60.935
  Top w0.138: 49.798,53.72 49.799,54.065 49.799,54.41 49.8,54.755 49.801,55.1 49.975,55.1
  Top w0.15: 40.39,61.48 40.416,61.576 40.622,61.782 ; 49.794,51.65 49.795,51.995 49.795,52.34 49.796,52.685 49.797,53.03 49.797,53.375 49.798,53.72
  Top w0.162: 40.403,60.935 40.41,60.662 ; 49.794,51.65 49.815,51.752
  Top w0.2: 40.622,61.782 40.829,61.988
  Top w0.25: U_MAIN.18@49.975,55.1 50.121,55.1 50.442,55.1 50.763,55.1 U_MAIN.18 50.619,55.15 50.525,55.15 50.431,55.15 50.337,55.15 50.244,55.15 50.15,55.15 50.056,55.15 U_MAIN.18@49.975,55.15 ; U_MAIN.11@49.976,51.65 50.057,51.65 50.15,51.65 50.244,51.65 50.338,51.65 50.432,51.65 50.525,51.65 50.619,51.65 U_MAIN.11 ; U_MAIN.11@50.182,51.65 50.447,51.65 U_MAIN.11 ; U_MAIN.11@51.198,51.65 50.955,51.65 U_MAIN.11 ; 51.45,51.65 51.369,51.65 51.275,51.65 51.181,51.65 51.088,51.65 50.994,51.65 50.9,51.65 50.806,51.65 U_MAIN.11 ; U_MAIN.50@63.351,51.65 63.432,51.65 63.525,51.65 63.619,51.65 63.713,51.65 63.807,51.65 63.9,51.65 63.994,51.65 U_MAIN.50 64.182,51.65 U_MAIN.50@64.276,51.65
  Top w0.262: 97.307,46.679 97.55,46.7 97.7,46.9 97.85,47.1 97.85,47.3 98,47.5 98.15,47.7
  Top w0.29: U_MAIN.50@64.276,51.65 64.37,51.608 U_MAIN.50@64.825,51.621
  Top w0.3: 100.775,52.65 100.837,52.65 100.931,52.65 101.025,52.65 101.119,52.65 101.213,52.65 101.306,52.65 J_DISPLAY.15 101.4,52.8 ; J_DISPLAY.16@101.4,53 J_DISPLAY.16
  Top w0.306: 75.51,36.566 75.639,36.802 75.828,36.952
  Top w0.312: 83.281,39.356 83.52,39.595 83.703,39.763 83.933,39.763 84.163,39.763 84.231,39.834 84.431,39.834 v1(84.428,39.831)
  Top w0.325: 51.78,47.207 51.751,47.01 v1(51.866,46.898) ; 75.399,36.308 75.51,36.566
  Top w0.35: U_LDO.5 37.717,58.41 37.984,58.557 38.251,58.704 38.4,58.138 38.925,57.262 39.625,57.262 39.975,57.438 39.975,59.013 39.539,59.513 39.6,59.5 39.625,59.45 39.975,59.8 40.197,60.171 40.416,60.39 40.41,60.662 ; 40.829,61.988 41.035,62.194 41.241,62.4 C_LDO_OUT.1 41.76,62.585 41.945,62.77 42.13,62.955 42.311,62.955 42.491,62.955 42.493,63.027 42.6,63.125 43.475,63.3 45.184,62.4 C_3V3_BULK.1 ; v1(46.607,60.406) 45.839,60.919 45.498,61.536 C_3V3_BULK.1 ; C_MCU_AVCC.1 49.963,51.65 49.975,51.65 ; v1(48.571,55.956) 48.695,55.832 48.746,55.832 48.91,55.668 C_MCU_DVCC1.1 49.963,55.15 U_MAIN.18@49.975,55.15 ; J_DEBUG.1 48.97,65.882 C_3V3_BULK.1 ; 49.815,51.752 49.917,51.65 U_MAIN.11@50.182,51.65 ; U_MAIN.11@51.198,51.65 51.7,51.575 51.809,51.281 51.809,50.958 51.809,50.635 51.809,50.312 51.809,49.989 51.809,49.666 51.809,49.343 51.809,49.02 51.809,48.697 51.809,48.373 51.809,48.05 51.809,47.727 51.809,47.404 51.78,47.207 ; 51.45,51.65 51.463,51.65 63.338,51.65 63.35,51.65 ; v1(53.2,41.6) 53.2,41.69 53.437,41.927 53.673,42.163 R_MCU_RESET.2 ; 64.825,51.621 65.62,51.643 C_MCU_DVCC2.1 65.89,51.325 65.89,51 65.89,50.675 65.89,50.35 65.89,50.024 65.89,49.699 65.89,49.374 65.89,49.049 65.89,48.724 65.89,48.399 65.89,48.074 66.137,47.826 66.385,47.579 66.632,47.332 66.88,47.084 67.127,46.837 67.374,46.589 67.622,46.342 67.869,46.095 68.117,45.847 68.364,45.6 68.611,45.352 68.859,45.105 69.106,44.858 69.354,44.61 69.601,44.363 69.848,44.115 70.096,43.868 70.343,43.621 70.591,43.373 70.838,43.126 71.085,42.878 71.333,42.631 71.58,42.384 71.828,42.136 72.075,41.889 72.322,41.641 72.57,41.394 72.817,41.147 73.065,40.899 73.312,40.652 73.559,40.404 73.807,40.157 74.054,39.91 74.302,39.662 74.549,39.415 74.796,39.167 75.044,38.92 75.5,38.8 76.375,38.8 76.568,38.908 76.91,38.91 76.43,38.92 76.67,39.16 R_DISPLAY_CS.2 ; C_EPD_BOOST_IN.1 75.118,35.58 75.298,35.76 75.288,36.049 75.399,36.308 ; 75.828,36.952 76.017,37.102 76.206,37.252 76.438,37.481 76.67,37.71 76.902,37.938 76.904,38.231 76.905,38.523 76.907,38.815 76.908,39.108 R_DISPLAY_CS.2 ; 83.281,39.356 83.042,39.117 82.803,38.878 82.564,38.639 L_EPD_BOOST.1 81.325,39.4 R_DISPLAY_RESET.2 79.731,39.221 79.552,39.042 79.373,38.863 79.35,38.8 78.65,38.8 77.795,38.863 77.446,38.863 77.268,39.042 77.089,39.221 R_DISPLAY_CS.2 ; v1(93.356,46.637) 93.703,46.637 94.049,46.637 94.396,46.637 94.742,46.637 95.089,46.637 95.435,46.637 95.782,46.637 96.129,46.637 96.475,46.637 96.822,46.637 97.064,46.658 97.307,46.679 ; 98.15,47.7 98.281,47.838 98.412,47.975 99,48.142 99.073,48.636 99.29,48.853 99.508,49.071 99.725,49.288 99.725,49.594 C_EPD_VDD_HF.1 99.725,52.288 C_EPD_VDD.1 99.863,52.65 100.65,52.65 100.744,52.65 100.775,52.65 ; 101.4,52.8 101.4,53
  Bottom w0.325: 51.867,46.551 v1(51.866,46.898)
  Bottom w0.35: v1(46.607,60.406) 46.637,60.379 48.571,58.445 v1(48.571,55.956) ; 51.867,46.551 51.867,46.204 51.868,45.857 51.868,45.509 51.869,45.162 51.869,44.815 51.87,44.467 51.87,44.12 51.871,43.773 51.871,43.426 51.872,43.078 52.093,42.857 52.315,42.636 52.536,42.414 52.757,42.193 52.979,41.972 53.2,41.75 v1(53.2,41.6) ; v1(84.428,39.831) 84.746,39.832 85.064,39.833 85.381,39.834 85.699,39.834 86.017,39.835 86.335,39.836 86.652,39.837 86.97,39.837 87.288,39.838 87.528,40.078 87.768,40.318 88.008,40.558 88.248,40.798 88.488,41.038 88.728,41.278 88.968,41.518 89.207,41.757 89.447,41.997 89.687,42.237 89.927,42.477 90.167,42.717 90.407,42.957 90.647,43.197 90.887,43.437 91.127,43.677 91.367,43.917 91.607,44.157 91.847,44.397 92.65,45.1 92.566,45.116 92.806,45.356 93.046,45.596 93.046,45.832 93.046,46.069 93.046,46.305 93.251,46.51 93.251,46.532 v1(93.356,46.637)
XT2_IN: U_MAIN.69 Y_XT2.1 | length 5.3
  Top w0.15: U_MAIN.69 58.158,44.72 v1(58.158,45.699) ; v1(58.97,42.814) 59.034,42.75 59.034,42.748 59.4,42.382 Y_XT2.1
  Bottom w0.15: v1(58.158,45.699) 58.196,45.661 58.196,45.492 58.196,43.588 v1(58.97,42.814)
XT2_OUT: U_MAIN.70 Y_XT2.3 | length 6.7
  Top w0.15: v1(55.354,41.739) 55.373,41.758 55.459,41.758 55.601,41.9 Y_XT2.3 ; v1(57.5,45.7) 57.5,44.862 U_MAIN.70
  Bottom w0.15: v1(55.354,41.739) 57.53,45.538 57.53,45.67 v1(57.5,45.7)
pads on no net: J_DISPLAY.1 J_DISPLAY.4 J_DISPLAY.6 J_DISPLAY.7 J_DISPLAY.19 J_DISPLAY.25 J_DISPLAY.26 J_USB.5 J_USB.11 J_USB.NPTH-1 J_USB.NPTH-2 U_LDO.4 U_MAIN.1 U_MAIN.2 U_MAIN.3 U_MAIN.4 U_MAIN.5 U_MAIN.6 U_MAIN.7 U_MAIN.8 U_MAIN.9 U_MAIN.10 U_MAIN.12 U_MAIN.13 U_MAIN.15 U_MAIN.16 U_MAIN.17 U_MAIN.21 U_MAIN.22 U_MAIN.23 U_MAIN.25 U_MAIN.26 U_MAIN.27 U_MAIN.28 U_MAIN.29 U_MAIN.30 U_MAIN.31 U_MAIN.32 U_MAIN.33 U_MAIN.34 U_MAIN.35 U_MAIN.36 U_MAIN.45 U_MAIN.46 U_MAIN.47 U_MAIN.48 U_MAIN.51 U_MAIN.52 U_MAIN.53 U_MAIN.54 U_MAIN.55 U_MAIN.56 U_MAIN.57 U_MAIN.58 U_MAIN.59 U_MAIN.60 U_MAIN.72 U_MAIN.73 U_MAIN.74 U_MAIN.75 U_MAIN.77 U_MAIN.78 U_MAIN.79 U_MAIN.80

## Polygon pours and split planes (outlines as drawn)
GND on Bottom (solid): 107.1,77.1 25.7,77.1 25.7,25.7 107.1,25.7
GND on Bottom (solid): 62.04,68.589 62.04,64.238 62.068,64.204 62.105,64.135 62.111,64.114 62.111,68.511 62.088,68.53
GND on Bottom (solid): 59.475,45.41 59.475,43.35 59.757,43.067 59.791,43.026 59.817,42.978 59.833,42.926 59.838,42.873 59.833,42.819 59.817,42.768 59.791,42.72 59.757,42.678 57.568,40.489 60.089,40.49 60.676,41.058 60.642,41.077 60.581,41.126 60.532,41.187 60.495,41.256 60.472,41.331 60.464,41.409 60.472,41.487 60.495,41.562 60.527,41.623 59.592,45.358 59.545,45.372 59.476,45.409
GND on Bottom (solid): 98.123,56.865 98.134,56.827 98.142,56.749 98.134,56.671 98.126,56.645 98.143,56.625 98.168,56.577 98.184,56.526 98.189,56.472 98.189,55.43 98.197,55.424 98.247,55.363 98.284,55.294 98.306,55.219 98.314,55.141 98.306,55.063 98.284,54.988 98.247,54.919 98.197,54.858 98.136,54.808 98.067,54.771 97.992,54.749 97.914,54.741 97.836,54.749 97.761,54.771 97.692,54.808 97.631,54.858 97.581,54.919 97.544,54.988 97.522,55.063 97.514,55.141 97.522,55.219 97.534,55.26 97.503,55.222 97.442,55.172 97.373,55.135 97.298,55.113 97.22,55.105 97.142,55.113 97.085,55.13 93.49,55.13 93.341,54.982 93.285,54.935 93.22,54.901 93.149,54.879 93.076,54.872 93.003,54.879 92.933,54.901 92.868,54.935 92.817,54.977 92.813,54.978 92.797,54.987 93.757,54.026 96.923,54.026 96.942,54.049 97.003,54.099 97.072,54.136 97.147,54.158 97.225,54.166 97.303,54.158 97.378,54.136 97.447,54.099 97.508,54.049 97.558,53.988 97.595,53.919 97.617,53.844 97.625,53.771 97.861,54.007 98.107,54.254 98.354,54.5 98.6,54.747 98.847,54.993 99.093,55.24 99.244,55.391 99.272,55.443 99.322,55.504 99.383,55.554 99.416,55.571
GND on Bottom (solid): 93.35,61.638 93.314,61.638 85.135,61.638 94.707,52.066 94.736,52.069 94.814,52.061 94.889,52.039 94.958,52.002 95.019,51.952 95.069,51.891 95.105,51.822 95.271,51.988 95.31,52.02 95.355,52.044 95.404,52.059 95.455,52.064 96.463,52.064 96.514,52.059 96.563,52.044 96.608,52.02 96.647,51.988 96.765,51.87 96.765,52.139 96.765,52.448 96.765,52.756 96.772,52.829 96.794,52.9 96.828,52.964 96.875,53.021 97.121,53.268 97.22,53.366 97.147,53.374 97.072,53.396 97.003,53.433 96.942,53.483 96.923,53.506 93.65,53.506 93.599,53.511 93.55,53.526 93.505,53.55 93.466,53.582 88.844,58.204 88.8,58.2 88.722,58.208 88.647,58.23 88.578,58.267 88.517,58.317 88.467,58.378 88.43,58.447 88.408,58.522 88.4,58.6 88.408,58.678 88.43,58.753 88.467,58.822 88.517,58.883 88.578,58.933 88.647,58.97 88.722,58.992 88.8,59 88.878,58.992 88.953,58.97 89.022,58.933 89.083,58.883 89.133,58.822 89.17,58.753 89.192,58.678 89.2,58.6 89.199,58.585 92.605,55.178 92.597,55.195 92.574,55.27 92.566,55.348 92.574,55.426 92.597,55.501 92.634,55.57 92.683,55.63 92.744,55.68 92.813,55.717 92.888,55.74 92.966,55.748 93.039,55.74 93.069,55.77 93.126,55.817 93.191,55.851 93.261,55.873 93.334,55.88 97.085,55.88 97.142,55.897 97.22,55.905 97.298,55.897 97.373,55.875 97.442,55.838 97.503,55.788 97.553,55.727 97.59,55.658 97.612,55.583 97.62,55.505 97.612,55.427 97.6,55.386 97.631,55.424 97.639,55.43 97.639,56.358 97.63,56.367 97.589,56.379 97.52,56.416 97.459,56.466 97.409,56.527 97.372,56.596 97.35,56.671 97.342,56.749 97.35,56.827 97.372,56.902 97.409,56.971 97.459,57.032 97.52,57.082 97.589,57.119 97.664,57.141 97.742,57.149 97.82,57.141 97.858,57.13
GND on Bottom (solid): 99.955,55.032 99.938,54.999 99.888,54.938 99.827,54.888 99.775,54.86 99.624,54.709 99.377,54.463 99.131,54.216 98.884,53.97 98.638,53.723 98.391,53.477 98.145,53.23 97.898,52.984 97.652,52.737 97.515,52.601 97.515,52.448 97.515,52.139 97.515,51.83 97.515,51.522 97.508,51.449 97.487,51.379 101.324,51.403 101.308,51.416 99.395,53.329 99.391,53.329 99.313,53.337 99.238,53.359 99.169,53.396 99.108,53.446 99.058,53.507 99.021,53.576 98.999,53.651 98.991,53.729 98.999,53.807 99.021,53.882 99.058,53.951 99.108,54.012 99.169,54.062 99.238,54.099 99.313,54.121 99.391,54.129 99.469,54.121 99.544,54.099 99.613,54.062 99.674,54.012 99.724,53.951 99.761,53.882 99.783,53.807 99.791,53.729 99.786,53.674 101.594,51.865 102.072,51.89 102.104,51.928 102.107,51.93 102.067,51.978 102.03,52.047 102.008,52.122 102,52.2 102.008,52.278 102.03,52.352 102.03,52.958
GND on Bottom (solid): 99.975,46.411 99.736,46.173 99.722,46.161 99.733,46.14 99.755,46.065 99.763,45.987 99.759,45.944 99.978,46.163 99.978,46.4

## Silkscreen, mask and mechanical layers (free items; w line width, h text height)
Top Overlay:
  text "2L • BOTTOM GND POUR" at 48.4,75.4 h0.48
  text "ER-CON24HT-1 • 4-WIRE SPI" at 84.4,75.4 h0.55
  text "ER-EPD0213-2B" at 81.4,28.9 h0.58
  text "QUICK CONFIGURE • SCREEN" at 66.4,27.4 h0.72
